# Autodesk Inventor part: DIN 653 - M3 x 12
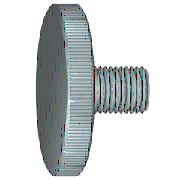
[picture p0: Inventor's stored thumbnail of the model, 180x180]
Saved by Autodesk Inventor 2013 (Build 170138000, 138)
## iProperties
Created: 2012-02
Part Number: DIN 653 - M3 x 12
Material: Stahl, weich
Description: Rändelschraube
Document SubType Name: Modeling
Standard: DIN 653
Designer: rYan
Standards Organization: DIN
Language: de-DE
Size Designation: M3 x 12
Categories: <MemberInstance><Categories><Category DisplayName="Verbindungselemente" InternalName="e4da775c-781d-43d5-af7c-5136215cf5a6" Mnemonic="FSTN"><Category DisplayNam
Density: 1 g/cm^3
IsCustomPart: 0
Author: rYan
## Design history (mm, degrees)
revolve "Körper" stored, may be unused: angle "d8" = 90 deg
node "IDS_WORKPLANE{1}"
workplane "Work Plane2"
body "Solid1"
feature "Gewinde" dims "d2" = 8.224 (= GEL - 0.092 x GD), "d3" = 0
chamfer "Fase1" distance "d10" = 0.3 (= PHH); stored, may be unused: angle "d11" = 45 deg (= FAWI), second distance "d38" = 0.3 (= PHH)
sketch "Skizze1"
  geometry: L1 (-2.5, 0)-(12, 0); L2 (12, 0)-(12, 5); L3 (11.673, 1.5)-(0, 1.5); L4 (0, -1.2)-(0, 7.2) reference; L5 (0, 1.5)-(0, 6); L6 (0, 6)-(-2.5, 6); L7 (-2.5, 6)-(-2.5, 0); L8 (-5.416, 0)-(14.997, 0) reference; A1 r 3.6 centre (8.4, 0) between (12, 0) and (11.673, 1.5)
  constraints: 13 end point, 2 perpendicular, 2 point on circle, 2 vertical alignment, 1 centre point, 1 collinear, 1 parallel, 1 point on line, 1 tangent
  dimensions: "d1" = 3 diameter of L3 L1 (= GD); "d6" = 12 diameter of L6 L1 (= KOD); "d7" = 2.5 distance between parallel lines of L5 L7 (= KOH); "d9" = 3.6 radius of A1 (= 1.2 x GD); "d41" = 12 distance between parallel lines of L2 L5 (= NLG)
other parameters: "GD" = 3 [user parameter; used in 3 equation terms], "NLG" = 12 [user parameter; used in 1 equation term], "GEL" = 8.5 [user parameter; used in 1 equation term], "KOD" = 12 [user parameter; used in 1 equation term], "KOH" = 2.5 [user parameter; used in 2 equation terms], "GAL" = 0.30673 (= 0.61345 x PTC) [user parameter], "d4" = 0, "SD" = 2 [user parameter], "LADI" = 3 (= NND) [user parameter], "PHH" = 0.3 [user parameter; used in 2 equation terms], "FAWI" = 45 deg [user parameter; used in 1 equation term], "d12" = -1.25 (= -0.5 x KOH), "T" = 0.5 [user parameter], "d39" = 0, "d42" = 0, "NND" = 3 [user parameter; used in 1 equation term], "PTC" = 0.5 [user parameter; used in 2 equation terms]
